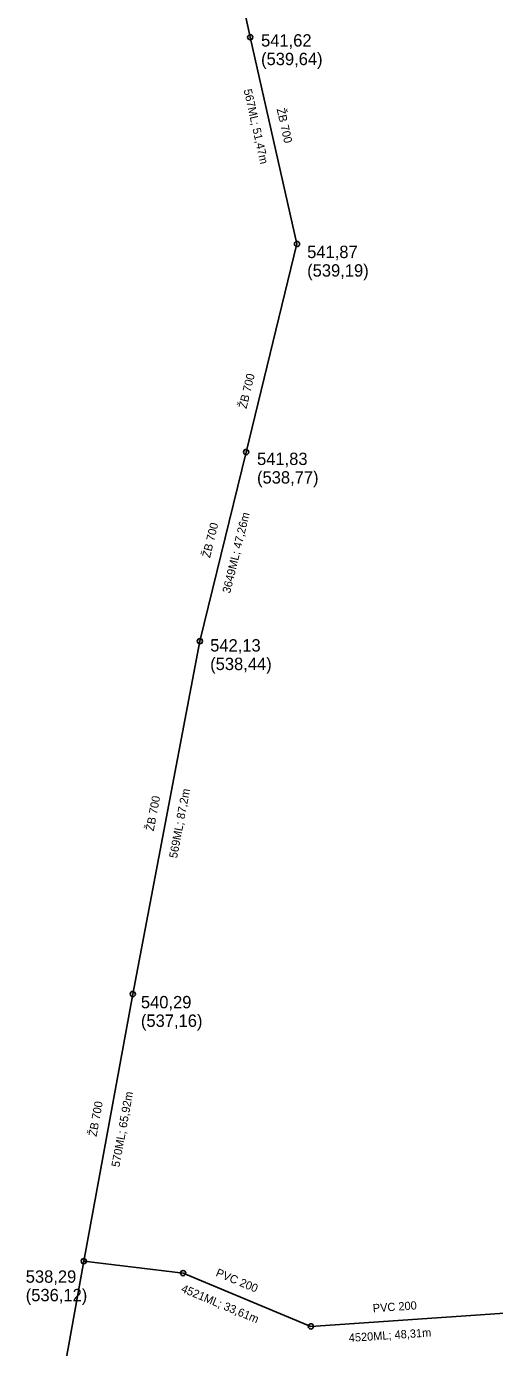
# Model space of a CAD drawing. Extents: x -867696 to -865033, y -1042522 to -1039817.
# Drawn here: x -865932.3 to -865818.6, y -1040840.1 to -1040519.4 of the extents above; entities that cross this region are included whole.
import ezdxf

# ---------------------------------------------------------------- set-up
doc = ezdxf.new("R2010")
doc.units = 0
for name, color, linetype in [('KN - jednotna', 7, 'Continuous'), ('KN - popis material', 7, 'Continuous'), ('KN - popis ostatni', 7, 'Continuous'), ('KN - popis usek delka', 7, 'Continuous'), ('KN - sachta komora', 7, 'Continuous'), ('KN - splaskova', 7, 'Continuous'), ('Level 1', 7, 'Continuous')]:
    doc.layers.add(name, color=color, linetype=linetype)

# ---------------------------------------------------------------- blocks, each defined once
blk = doc.blocks.new('100.M')
at = {"layer": 'Level 1'}
blk.add_circle((0, 0), 1.27, dxfattribs=at)

msp = doc.modelspace()

# ---------------------------------------------------------------- linework, layer by layer
at = {"layer": 'KN - jednotna'}
for points in [[(-865893.469, -1040450.027), (-865877.948, -1040521.978)], [(-865877.948, -1040521.978), (-865866.598, -1040572.178)], [(-865866.598, -1040572.178), (-865878.946, -1040622.691)], [(-865878.946, -1040622.691), (-865890.167, -1040668.597)], [(-865890.167, -1040668.597), (-865906.468, -1040754.259)], [(-865906.468, -1040754.259), (-865918.379, -1040819.098)], [(-865918.379, -1040819.098), (-865929.417, -1040880.668)]]:
    msp.add_lwpolyline(points, dxfattribs=at)
at = {"layer": 'KN - splaskova'}
for points in [[(-865894.243, -1040822.005), (-865918.379, -1040819.098)], [(-865863.216, -1040834.935), (-865894.243, -1040822.005)], [(-865815.012, -1040831.68), (-865863.216, -1040834.935)]]:
    msp.add_lwpolyline(points, dxfattribs=at)

# ---------------------------------------------------------------- block references
at = {"layer": 'KN - sachta komora'}
for p, xscale, yscale, rotation in [((-865877.948, -1040521.978), 0.4999999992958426, 0.4999999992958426, 103.00000027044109), ((-865866.598, -1040572.178), 0.5, 0.5, -90), ((-865878.946, -1040622.691), 0.4999999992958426, 0.4999999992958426, -103.00000027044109), ((-865890.167, -1040668.597), 0.5000000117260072, 0.5000000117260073, -101.99999938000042), ((-865906.468, -1040754.259), 0.49999998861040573, 0.4999999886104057, -100.00000028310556), ((-865918.379, -1040819.098), 0.49999998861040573, 0.4999999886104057, -100.00000028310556), ((-865894.243, -1040822.005), 0.5004924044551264, 0.5004924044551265, 165.77567372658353), ((-865863.216, -1040834.935), 0.5041888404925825, 0.5041888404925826, 168.37362119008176)]:
    msp.add_blockref('100.M', p, dxfattribs=dict(at, xscale=xscale, yscale=yscale, rotation=rotation))

# ---------------------------------------------------------------- texts
at = {"layer": 'KN - popis material'}
for s, rotation, p in [('ŽB 700', 282.74, (-865871.538, -1040539.445)), ('ŽB 700', 76.26, (-865878.873, -1040612.285)), ('ŽB 700', 76.26, (-865887.724, -1040648.492)), ('ŽB 700', 79.23, (-865901.405, -1040714.818)), ('ŽB 700', 79.59, (-865915.282, -1040788.957)), ('PVC 200', 337.38, (-865886.478, -1040822.642)), ('PVC 200', 3.86, (-865848.125, -1040831.51))]:
    msp.add_text(s, height=2, rotation=rotation, dxfattribs=at).set_placement(p)
at = {"layer": 'KN - popis ostatni'}
for s, p in [('541,62 ', (-865875.318, -1040524.258)), ('(539,64)', (-865875.318, -1040528.758)), ('541,87 ', (-865864.118, -1040575.598)), ('(539,19)', (-865864.118, -1040580.098)), ('541,83 ', (-865876.296, -1040625.831)), ('(538,77)', (-865876.296, -1040630.331)), ('542,13 ', (-865887.677, -1040671.107)), ('(538,44)', (-865887.677, -1040675.607)), ('540,29 ', (-865904.498, -1040757.719)), ('(537,16)', (-865904.498, -1040762.219)), ('538,29 ', (-865932.469, -1040824.328)), ('(536,12)', (-865932.469, -1040828.828))]:
    msp.add_text(s, height=3, dxfattribs=at).set_placement(p)
at = {"layer": 'KN - popis usek delka'}
for s, rotation, p in [('567ML; 51,47m', 282.74, (-865879.56, -1040534.8)), ('3649ML; 47,26m', 76.26, (-865882.828, -1040657.101)), ('569ML; 87,2m', 79.23, (-865895.734, -1040721.394)), ('570ML; 65,92m', 79.59, (-865909.733, -1040796.382)), ('4521ML; 33,61m', 337.38, (-865894.908, -1040826.495)), ('4520ML; 48,31m', 3.86, (-865853.952, -1040838.719))]:
    msp.add_text(s, height=1.99999, rotation=rotation, dxfattribs=at).set_placement(p)

doc.saveas('drawing.dxf')
